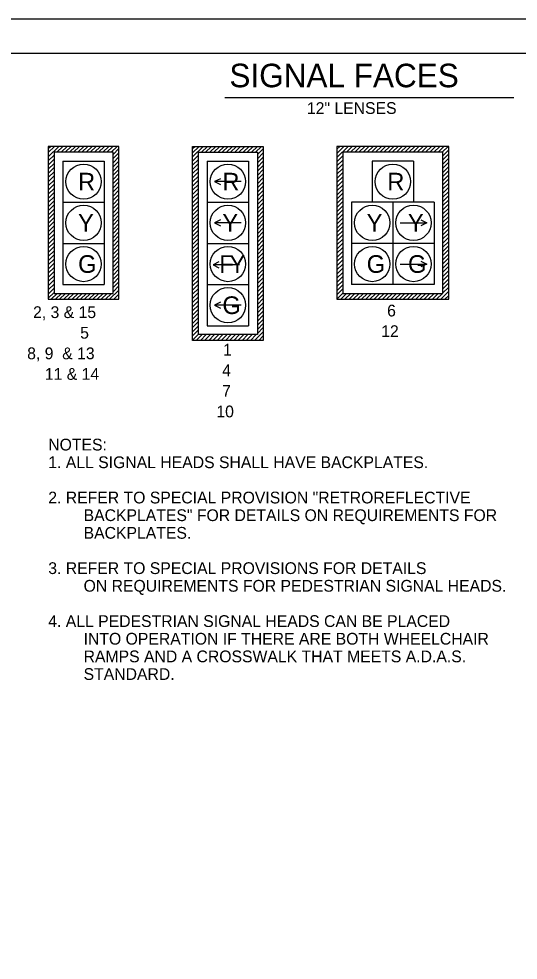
# Model space of a CAD drawing. Extents: x 1712074 to 1713074, y 558397 to 559037.
# Drawn here: x 1712248.4 to 1712417.9, y 558716.9 to 559037 of the extents above; entities that cross this region are included whole.
import ezdxf

# ---------------------------------------------------------------- set-up
doc = ezdxf.new("R2010")
doc.units = 0
for name, color, linetype in [('R_Border', 7, 'Continuous'), ('R_No Plot', 7, 'Continuous'), ('T_Drafting', 7, 'Continuous'), ('T_Notes', 7, 'Continuous')]:
    doc.layers.add(name, color=color, linetype=linetype)

msp = doc.modelspace()

# ---------------------------------------------------------------- linework, layer by layer
at = {"layer": 'R_Border'}
msp.add_line((1712111.35, 559025.27), (1713059.89, 559025.27), dxfattribs=at)
at = {"layer": 'R_No Plot'}
msp.add_line((1712074.14, 559036.95), (1713074.14, 559036.95), dxfattribs=at)
msp.add_lwpolyline([(1712074.12, 559036.95), (1713074.14, 559036.95), (1713074.14, 558396.94), (1712074.12, 558396.94)], close=True, dxfattribs=at)
at = {"layer": 'T_Drafting'}
for p, q in [((1712282.36, 558993.6), (1712258.36, 558993.6)), ((1712258.36, 558993.6), (1712258.36, 558941.6)), ((1712258.36, 558990.05), (1712261.91, 558993.6)), ((1712258.36, 558991.46), (1712260.49, 558993.6)), ((1712258.36, 558992.88), (1712259.08, 558993.6)), ((1712261.32, 558991.6), (1712263.32, 558993.6)), ((1712262.73, 558991.6), (1712264.73, 558993.6)), ((1712264.15, 558991.6), (1712266.15, 558993.6)), ((1712265.56, 558991.6), (1712267.56, 558993.6)), ((1712266.98, 558991.6), (1712268.98, 558993.6)), ((1712268.39, 558991.6), (1712270.39, 558993.6)), ((1712269.81, 558991.6), (1712271.81, 558993.6)), ((1712271.22, 558991.6), (1712273.22, 558993.6)), ((1712272.63, 558991.6), (1712274.63, 558993.6)), ((1712274.05, 558991.6), (1712276.05, 558993.6)), ((1712275.46, 558991.6), (1712277.46, 558993.6)), ((1712276.88, 558991.6), (1712278.88, 558993.6)), ((1712278.29, 558991.6), (1712280.29, 558993.6)), ((1712279.71, 558991.6), (1712281.71, 558993.6)), ((1712282.36, 558941.6), (1712282.36, 558993.6)), ((1712307.36, 558927.6), (1712307.36, 558993.6)), ((1712307.36, 558993.6), (1712331.36, 558993.6)), ((1712307.36, 558989.99), (1712310.97, 558993.6)), ((1712307.36, 558991.4), (1712309.55, 558993.6)), ((1712307.36, 558992.82), (1712308.14, 558993.6)), ((1712310.38, 558991.6), (1712312.38, 558993.6)), ((1712311.79, 558991.6), (1712313.79, 558993.6)), ((1712313.21, 558991.6), (1712315.21, 558993.6)), ((1712314.62, 558991.6), (1712316.62, 558993.6)), ((1712316.04, 558991.6), (1712318.04, 558993.6)), ((1712317.45, 558991.6), (1712319.45, 558993.6)), ((1712318.87, 558991.6), (1712320.87, 558993.6)), ((1712320.28, 558991.6), (1712322.28, 558993.6)), ((1712321.69, 558991.6), (1712323.69, 558993.6)), ((1712323.11, 558991.6), (1712325.11, 558993.6)), ((1712324.52, 558991.6), (1712326.52, 558993.6)), ((1712325.94, 558991.6), (1712327.94, 558993.6)), ((1712327.35, 558991.6), (1712329.35, 558993.6)), ((1712328.77, 558991.6), (1712330.77, 558993.6)), ((1712331.36, 558993.6), (1712331.36, 558927.6)), ((1712394.36, 558993.6), (1712356.36, 558993.6)), ((1712356.36, 558993.6), (1712356.36, 558941.6)), ((1712356.36, 558989.78), (1712360.18, 558993.6)), ((1712356.36, 558991.19), (1712358.77, 558993.6)), ((1712356.36, 558992.6), (1712357.35, 558993.6)), ((1712359.6, 558991.6), (1712361.6, 558993.6)), ((1712361.01, 558991.6), (1712363.01, 558993.6)), ((1712362.42, 558991.6), (1712364.42, 558993.6)), ((1712363.84, 558991.6), (1712365.84, 558993.6)), ((1712365.25, 558991.6), (1712367.25, 558993.6)), ((1712366.67, 558991.6), (1712368.67, 558993.6)), ((1712368.08, 558991.6), (1712370.08, 558993.6)), ((1712369.49, 558991.6), (1712371.49, 558993.6)), ((1712370.91, 558991.6), (1712372.91, 558993.6)), ((1712372.32, 558991.6), (1712374.32, 558993.6)), ((1712373.74, 558991.6), (1712375.74, 558993.6)), ((1712375.15, 558991.6), (1712377.15, 558993.6)), ((1712376.57, 558991.6), (1712378.57, 558993.6)), ((1712377.98, 558991.6), (1712379.98, 558993.6)), ((1712379.39, 558991.6), (1712381.39, 558993.6)), ((1712380.81, 558991.6), (1712382.81, 558993.6)), ((1712382.22, 558991.6), (1712384.22, 558993.6)), ((1712383.64, 558991.6), (1712385.64, 558993.6)), ((1712385.05, 558991.6), (1712387.05, 558993.6)), ((1712386.47, 558991.6), (1712388.47, 558993.6)), ((1712387.88, 558991.6), (1712389.88, 558993.6)), ((1712389.29, 558991.6), (1712391.29, 558993.6)), ((1712390.71, 558991.6), (1712392.71, 558993.6)), ((1712392.12, 558991.6), (1712394.12, 558993.6)), ((1712394.36, 558941.6), (1712394.36, 558993.6)), ((1712258.36, 558988.64), (1712260.36, 558990.64)), ((1712280.36, 558990.84), (1712282.36, 558992.84)), ((1712280.36, 558989.42), (1712282.36, 558991.42)), ((1712307.36, 558988.58), (1712309.36, 558990.58)), ((1712329.36, 558990.78), (1712331.36, 558992.78)), ((1712329.36, 558989.36), (1712331.36, 558991.36)), ((1712392.36, 558990.42), (1712394.36, 558992.42)), ((1712392.36, 558989.01), (1712394.36, 558991.01)), ((1712258.36, 558987.22), (1712260.36, 558989.22)), ((1712258.36, 558985.81), (1712260.36, 558987.81)), ((1712263.36, 558988.6), (1712277.36, 558988.6)), ((1712263.36, 558988.6), (1712263.36, 558974.6)), ((1712277.36, 558988.6), (1712277.36, 558974.6)), ((1712280.36, 558988.01), (1712282.36, 558990.01)), ((1712280.36, 558986.59), (1712282.36, 558988.59)), ((1712280.36, 558985.18), (1712282.36, 558987.18)), ((1712307.36, 558987.16), (1712309.36, 558989.16)), ((1712307.36, 558985.75), (1712309.36, 558987.75)), ((1712312.36, 558988.6), (1712326.36, 558988.6)), ((1712312.36, 558988.6), (1712312.36, 558974.6)), ((1712326.36, 558988.6), (1712326.36, 558974.6)), ((1712329.36, 558987.95), (1712331.36, 558989.95)), ((1712329.36, 558986.53), (1712331.36, 558988.53)), ((1712356.36, 558988.36), (1712358.36, 558990.36)), ((1712356.36, 558986.95), (1712358.36, 558988.95)), ((1712356.36, 558985.53), (1712358.36, 558987.53)), ((1712382.36, 558988.6), (1712368.36, 558988.6)), ((1712368.36, 558988.6), (1712368.36, 558974.6)), ((1712382.36, 558988.6), (1712382.36, 558974.6)), ((1712392.36, 558987.59), (1712394.36, 558989.59)), ((1712392.36, 558986.18), (1712394.36, 558988.18)), ((1712258.36, 558984.39), (1712260.36, 558986.39)), ((1712258.36, 558982.98), (1712260.36, 558984.98)), ((1712280.36, 558983.77), (1712282.36, 558985.77)), ((1712280.36, 558982.35), (1712282.36, 558984.35)), ((1712307.36, 558984.33), (1712309.36, 558986.33)), ((1712307.36, 558982.92), (1712309.36, 558984.92)), ((1712329.36, 558985.12), (1712331.36, 558987.12)), ((1712329.36, 558983.71), (1712331.36, 558985.71)), ((1712329.36, 558982.29), (1712331.36, 558984.29)), ((1712356.36, 558984.12), (1712358.36, 558986.12)), ((1712356.36, 558982.7), (1712358.36, 558984.7)), ((1712392.36, 558984.76), (1712394.36, 558986.76)), ((1712392.36, 558983.35), (1712394.36, 558985.35)), ((1712258.36, 558981.56), (1712260.36, 558983.56)), ((1712258.36, 558980.15), (1712260.36, 558982.15)), ((1712280.36, 558980.94), (1712282.36, 558982.94)), ((1712280.36, 558979.52), (1712282.36, 558981.52)), ((1712307.36, 558981.5), (1712309.36, 558983.5)), ((1712307.36, 558980.09), (1712309.36, 558982.09)), ((1712323.86, 558981.6), (1712314.86, 558981.6)), ((1712329.36, 558980.88), (1712331.36, 558982.88)), ((1712329.36, 558979.46), (1712331.36, 558981.46)), ((1712356.36, 558981.29), (1712358.36, 558983.29)), ((1712356.36, 558979.88), (1712358.36, 558981.88)), ((1712392.36, 558981.93), (1712394.36, 558983.93)), ((1712392.36, 558980.52), (1712394.36, 558982.52)), ((1712392.36, 558979.11), (1712394.36, 558981.11)), ((1712258.36, 558978.74), (1712260.36, 558980.74)), ((1712258.36, 558977.32), (1712260.36, 558979.32)), ((1712258.36, 558975.91), (1712260.36, 558977.91)), ((1712280.36, 558978.11), (1712282.36, 558980.11)), ((1712280.36, 558976.69), (1712282.36, 558978.69)), ((1712307.36, 558978.68), (1712309.36, 558980.68)), ((1712307.36, 558977.26), (1712309.36, 558979.26)), ((1712307.36, 558975.85), (1712309.36, 558977.85)), ((1712329.36, 558978.05), (1712331.36, 558980.05)), ((1712329.36, 558976.63), (1712331.36, 558978.63)), ((1712356.36, 558978.46), (1712358.36, 558980.46)), ((1712356.36, 558977.05), (1712358.36, 558979.05)), ((1712356.36, 558975.63), (1712358.36, 558977.63)), ((1712392.36, 558977.69), (1712394.36, 558979.69)), ((1712392.36, 558976.28), (1712394.36, 558978.28)), ((1712258.36, 558974.49), (1712260.36, 558976.49)), ((1712258.36, 558973.08), (1712260.36, 558975.08)), ((1712263.36, 558974.6), (1712277.36, 558974.6)), ((1712263.36, 558974.6), (1712263.36, 558960.6)), ((1712277.36, 558974.6), (1712277.36, 558960.6)), ((1712280.36, 558975.28), (1712282.36, 558977.28)), ((1712280.36, 558973.87), (1712282.36, 558975.87)), ((1712280.36, 558972.45), (1712282.36, 558974.45)), ((1712307.36, 558974.43), (1712309.36, 558976.43)), ((1712307.36, 558973.02), (1712309.36, 558975.02)), ((1712312.36, 558974.6), (1712326.36, 558974.6)), ((1712312.36, 558974.6), (1712312.36, 558960.6)), ((1712326.36, 558974.6), (1712326.36, 558960.6)), ((1712329.36, 558975.22), (1712331.36, 558977.22)), ((1712329.36, 558973.81), (1712331.36, 558975.81)), ((1712329.36, 558972.39), (1712331.36, 558974.39)), ((1712356.36, 558974.22), (1712358.36, 558976.22)), ((1712356.36, 558972.8), (1712358.36, 558974.8)), ((1712375.36, 558974.6), (1712361.36, 558974.6)), ((1712361.36, 558974.6), (1712361.36, 558960.6)), ((1712375.36, 558974.6), (1712375.36, 558960.6)), ((1712389.36, 558974.6), (1712375.36, 558974.6)), ((1712375.36, 558974.6), (1712375.36, 558960.6)), ((1712389.36, 558974.6), (1712389.36, 558960.6)), ((1712392.36, 558974.86), (1712394.36, 558976.86)), ((1712392.36, 558973.45), (1712394.36, 558975.45)), ((1712258.36, 558971.67), (1712260.36, 558973.67)), ((1712258.36, 558970.25), (1712260.36, 558972.25)), ((1712280.36, 558971.04), (1712282.36, 558973.04)), ((1712280.36, 558969.62), (1712282.36, 558971.62)), ((1712307.36, 558971.6), (1712309.36, 558973.6)), ((1712307.36, 558970.19), (1712309.36, 558972.19)), ((1712329.36, 558970.98), (1712331.36, 558972.98)), ((1712329.36, 558969.56), (1712331.36, 558971.56)), ((1712356.36, 558971.39), (1712358.36, 558973.39)), ((1712356.36, 558969.98), (1712358.36, 558971.98)), ((1712392.36, 558972.04), (1712394.36, 558974.04)), ((1712392.36, 558970.62), (1712394.36, 558972.62)), ((1712392.36, 558969.21), (1712394.36, 558971.21)), ((1712258.36, 558968.84), (1712260.36, 558970.84)), ((1712258.36, 558967.42), (1712260.36, 558969.42)), ((1712258.36, 558966.01), (1712260.36, 558968.01)), ((1712280.36, 558968.21), (1712282.36, 558970.21)), ((1712280.36, 558966.8), (1712282.36, 558968.8)), ((1712307.36, 558968.78), (1712309.36, 558970.78)), ((1712307.36, 558967.36), (1712309.36, 558969.36)), ((1712329.36, 558968.15), (1712331.36, 558970.15)), ((1712329.36, 558966.73), (1712331.36, 558968.73)), ((1712356.36, 558968.56), (1712358.36, 558970.56)), ((1712356.36, 558967.15), (1712358.36, 558969.15)), ((1712392.36, 558967.79), (1712394.36, 558969.79)), ((1712392.36, 558966.38), (1712394.36, 558968.38)), ((1712258.36, 558964.59), (1712260.36, 558966.59)), ((1712258.36, 558963.18), (1712260.36, 558965.18)), ((1712280.36, 558965.38), (1712282.36, 558967.38)), ((1712280.36, 558963.97), (1712282.36, 558965.97)), ((1712307.36, 558965.95), (1712309.36, 558967.95)), ((1712307.36, 558964.53), (1712309.36, 558966.53)), ((1712307.36, 558963.12), (1712309.36, 558965.12)), ((1712323.86, 558967.6), (1712314.86, 558967.6)), ((1712329.36, 558965.32), (1712331.36, 558967.32)), ((1712329.36, 558963.91), (1712331.36, 558965.91)), ((1712356.36, 558965.73), (1712358.36, 558967.73)), ((1712356.36, 558964.32), (1712358.36, 558966.32)), ((1712356.36, 558962.91), (1712358.36, 558964.91)), ((1712377.86, 558967.6), (1712386.86, 558967.6)), ((1712392.36, 558964.96), (1712394.36, 558966.96)), ((1712392.36, 558963.55), (1712394.36, 558965.55)), ((1712258.36, 558961.77), (1712260.36, 558963.77)), ((1712258.36, 558960.35), (1712260.36, 558962.35)), ((1712280.36, 558962.55), (1712282.36, 558964.55)), ((1712280.36, 558961.14), (1712282.36, 558963.14)), ((1712280.36, 558959.72), (1712282.36, 558961.72)), ((1712307.36, 558961.71), (1712309.36, 558963.71)), ((1712307.36, 558960.29), (1712309.36, 558962.29)), ((1712329.36, 558962.49), (1712331.36, 558964.49)), ((1712329.36, 558961.08), (1712331.36, 558963.08)), ((1712329.36, 558959.66), (1712331.36, 558961.66)), ((1712356.36, 558961.49), (1712358.36, 558963.49)), ((1712356.36, 558960.08), (1712358.36, 558962.08)), ((1712392.36, 558962.14), (1712394.36, 558964.14)), ((1712392.36, 558960.72), (1712394.36, 558962.72)), ((1712258.36, 558958.94), (1712260.36, 558960.94)), ((1712258.36, 558957.52), (1712260.36, 558959.52)), ((1712263.36, 558960.6), (1712277.36, 558960.6)), ((1712263.36, 558960.6), (1712263.36, 558946.6)), ((1712277.36, 558960.6), (1712277.36, 558946.6)), ((1712280.36, 558958.31), (1712282.36, 558960.31)), ((1712280.36, 558956.9), (1712282.36, 558958.9)), ((1712307.36, 558958.88), (1712309.36, 558960.88)), ((1712307.36, 558957.46), (1712309.36, 558959.46)), ((1712312.36, 558960.6), (1712326.36, 558960.6)), ((1712312.36, 558960.6), (1712312.36, 558946.6)), ((1712326.36, 558960.6), (1712326.36, 558946.6)), ((1712329.36, 558958.25), (1712331.36, 558960.25)), ((1712329.36, 558956.84), (1712331.36, 558958.84)), ((1712356.36, 558958.66), (1712358.36, 558960.66)), ((1712356.36, 558957.25), (1712358.36, 558959.25)), ((1712375.36, 558960.6), (1712361.36, 558960.6)), ((1712361.36, 558960.6), (1712361.36, 558946.6)), ((1712389.36, 558960.6), (1712375.36, 558960.6)), ((1712375.36, 558960.6), (1712375.36, 558946.6)), ((1712375.36, 558960.6), (1712375.36, 558946.6)), ((1712389.36, 558960.6), (1712389.36, 558946.6)), ((1712392.36, 558959.31), (1712394.36, 558961.31)), ((1712392.36, 558957.89), (1712394.36, 558959.89)), ((1712392.36, 558956.48), (1712394.36, 558958.48)), ((1712258.36, 558956.11), (1712260.36, 558958.11)), ((1712258.36, 558954.69), (1712260.36, 558956.69)), ((1712258.36, 558953.28), (1712260.36, 558955.28)), ((1712280.36, 558955.48), (1712282.36, 558957.48)), ((1712280.36, 558954.07), (1712282.36, 558956.07)), ((1712307.36, 558956.05), (1712309.36, 558958.05)), ((1712307.36, 558954.63), (1712309.36, 558956.63)), ((1712307.36, 558953.22), (1712309.36, 558955.22)), ((1712329.36, 558955.42), (1712331.36, 558957.42)), ((1712329.36, 558954.01), (1712331.36, 558956.01)), ((1712356.36, 558955.83), (1712358.36, 558957.83)), ((1712356.36, 558954.42), (1712358.36, 558956.42)), ((1712392.36, 558955.06), (1712394.36, 558957.06)), ((1712392.36, 558953.65), (1712394.36, 558955.65)), ((1712258.36, 558951.87), (1712260.36, 558953.87)), ((1712258.36, 558950.45), (1712260.36, 558952.45)), ((1712280.36, 558952.65), (1712282.36, 558954.65)), ((1712280.36, 558951.24), (1712282.36, 558953.24)), ((1712307.36, 558951.81), (1712309.36, 558953.81)), ((1712307.36, 558950.39), (1712309.36, 558952.39)), ((1712323.33, 558953.32), (1712314.33, 558953.32)), ((1712329.36, 558952.59), (1712331.36, 558954.59)), ((1712329.36, 558951.18), (1712331.36, 558953.18)), ((1712356.36, 558953.01), (1712358.36, 558955.01)), ((1712356.36, 558951.59), (1712358.36, 558953.59)), ((1712356.36, 558950.18), (1712358.36, 558952.18)), ((1712377.86, 558953.6), (1712386.86, 558953.6)), ((1712392.36, 558952.24), (1712394.36, 558954.24)), ((1712392.36, 558950.82), (1712394.36, 558952.82)), ((1712258.36, 558949.04), (1712260.36, 558951.04)), ((1712258.36, 558947.62), (1712260.36, 558949.62)), ((1712280.36, 558949.82), (1712282.36, 558951.82)), ((1712280.36, 558948.41), (1712282.36, 558950.41)), ((1712280.36, 558947), (1712282.36, 558949)), ((1712307.36, 558948.98), (1712309.36, 558950.98)), ((1712307.36, 558947.56), (1712309.36, 558949.56)), ((1712329.36, 558949.76), (1712331.36, 558951.76)), ((1712329.36, 558948.35), (1712331.36, 558950.35)), ((1712329.36, 558946.94), (1712331.36, 558948.94)), ((1712356.36, 558948.76), (1712358.36, 558950.76)), ((1712356.36, 558947.35), (1712358.36, 558949.35)), ((1712392.36, 558949.41), (1712394.36, 558951.41)), ((1712392.36, 558947.99), (1712394.36, 558949.99)), ((1712258.36, 558946.21), (1712260.36, 558948.21)), ((1712258.36, 558944.8), (1712260.36, 558946.8)), ((1712263.36, 558946.6), (1712277.36, 558946.6)), ((1712280.36, 558945.58), (1712282.36, 558947.58)), ((1712280.36, 558944.17), (1712282.36, 558946.17)), ((1712307.36, 558946.15), (1712309.36, 558948.15)), ((1712307.36, 558944.73), (1712309.36, 558946.73)), ((1712312.36, 558946.6), (1712326.36, 558946.6)), ((1712312.36, 558946.6), (1712312.36, 558932.6)), ((1712326.36, 558946.6), (1712326.36, 558932.6)), ((1712329.36, 558945.52), (1712331.36, 558947.52)), ((1712329.36, 558944.11), (1712331.36, 558946.11)), ((1712356.36, 558945.93), (1712358.36, 558947.93)), ((1712356.36, 558944.52), (1712358.36, 558946.52)), ((1712375.36, 558946.6), (1712361.36, 558946.6)), ((1712389.36, 558946.6), (1712375.36, 558946.6)), ((1712392.36, 558946.58), (1712394.36, 558948.58)), ((1712392.36, 558945.17), (1712394.36, 558947.17)), ((1712392.36, 558943.75), (1712394.36, 558945.75)), ((1712258.36, 558943.38), (1712260.36, 558945.38)), ((1712258.36, 558941.97), (1712260.36, 558943.97)), ((1712259.4, 558941.6), (1712261.4, 558943.6)), ((1712260.82, 558941.6), (1712262.82, 558943.6)), ((1712262.23, 558941.6), (1712264.23, 558943.6)), ((1712263.65, 558941.6), (1712265.65, 558943.6)), ((1712265.06, 558941.6), (1712267.06, 558943.6)), ((1712266.47, 558941.6), (1712268.47, 558943.6)), ((1712267.89, 558941.6), (1712269.89, 558943.6)), ((1712269.3, 558941.6), (1712271.3, 558943.6)), ((1712270.72, 558941.6), (1712272.72, 558943.6)), ((1712272.13, 558941.6), (1712274.13, 558943.6)), ((1712273.55, 558941.6), (1712275.55, 558943.6)), ((1712274.96, 558941.6), (1712276.96, 558943.6)), ((1712276.37, 558941.6), (1712278.37, 558943.6)), ((1712277.79, 558941.6), (1712279.79, 558943.6)), ((1712279.2, 558941.6), (1712282.36, 558944.75)), ((1712280.62, 558941.6), (1712282.36, 558943.34)), ((1712307.36, 558943.32), (1712309.36, 558945.32)), ((1712307.36, 558941.91), (1712309.36, 558943.91)), ((1712307.36, 558940.49), (1712309.36, 558942.49)), ((1712329.36, 558942.69), (1712331.36, 558944.69)), ((1712329.36, 558941.28), (1712331.36, 558943.28)), ((1712356.36, 558943.11), (1712358.36, 558945.11)), ((1712356.36, 558941.69), (1712358.36, 558943.69)), ((1712357.68, 558941.6), (1712359.68, 558943.6)), ((1712359.09, 558941.6), (1712361.09, 558943.6)), ((1712360.51, 558941.6), (1712362.51, 558943.6)), ((1712361.92, 558941.6), (1712363.92, 558943.6)), ((1712363.34, 558941.6), (1712365.34, 558943.6)), ((1712364.75, 558941.6), (1712366.75, 558943.6)), ((1712366.16, 558941.6), (1712368.16, 558943.6)), ((1712367.58, 558941.6), (1712369.58, 558943.6)), ((1712368.99, 558941.6), (1712370.99, 558943.6)), ((1712370.41, 558941.6), (1712372.41, 558943.6)), ((1712371.82, 558941.6), (1712373.82, 558943.6)), ((1712373.23, 558941.6), (1712375.23, 558943.6)), ((1712374.65, 558941.6), (1712376.65, 558943.6)), ((1712376.06, 558941.6), (1712378.06, 558943.6)), ((1712377.48, 558941.6), (1712379.48, 558943.6)), ((1712378.89, 558941.6), (1712380.89, 558943.6)), ((1712380.31, 558941.6), (1712382.31, 558943.6)), ((1712381.72, 558941.6), (1712383.72, 558943.6)), ((1712383.13, 558941.6), (1712385.13, 558943.6)), ((1712384.55, 558941.6), (1712386.55, 558943.6)), ((1712385.96, 558941.6), (1712387.96, 558943.6)), ((1712387.38, 558941.6), (1712389.38, 558943.6)), ((1712388.79, 558941.6), (1712390.79, 558943.6)), ((1712390.21, 558941.6), (1712392.21, 558943.6)), ((1712391.62, 558941.6), (1712394.36, 558944.34)), ((1712393.03, 558941.6), (1712394.36, 558942.92)), ((1712258.36, 558941.6), (1712282.36, 558941.6)), ((1712282.03, 558941.6), (1712282.36, 558941.93)), ((1712307.36, 558939.08), (1712309.36, 558941.08)), ((1712307.36, 558937.66), (1712309.36, 558939.66)), ((1712323.86, 558939.6), (1712314.86, 558939.6)), ((1712329.36, 558939.86), (1712331.36, 558941.86)), ((1712329.36, 558938.45), (1712331.36, 558940.45)), ((1712356.36, 558941.6), (1712394.36, 558941.6)), ((1712307.36, 558936.25), (1712309.36, 558938.25)), ((1712307.36, 558934.84), (1712309.36, 558936.84)), ((1712329.36, 558937.04), (1712331.36, 558939.04)), ((1712329.36, 558935.62), (1712331.36, 558937.62)), ((1712329.36, 558934.21), (1712331.36, 558936.21)), ((1712307.36, 558933.42), (1712309.36, 558935.42)), ((1712307.36, 558932.01), (1712309.36, 558934.01)), ((1712329.36, 558932.79), (1712331.36, 558934.79)), ((1712329.36, 558931.38), (1712331.36, 558933.38)), ((1712307.36, 558930.59), (1712309.36, 558932.59)), ((1712307.36, 558929.18), (1712309.36, 558931.18)), ((1712307.36, 558927.76), (1712309.36, 558929.76)), ((1712308.61, 558927.6), (1712310.61, 558929.6)), ((1712310.02, 558927.6), (1712312.02, 558929.6)), ((1712311.43, 558927.6), (1712313.43, 558929.6)), ((1712312.36, 558932.6), (1712326.36, 558932.6)), ((1712312.85, 558927.6), (1712314.85, 558929.6)), ((1712314.26, 558927.6), (1712316.26, 558929.6)), ((1712315.68, 558927.6), (1712317.68, 558929.6)), ((1712317.09, 558927.6), (1712319.09, 558929.6)), ((1712318.51, 558927.6), (1712320.51, 558929.6)), ((1712319.92, 558927.6), (1712321.92, 558929.6)), ((1712321.33, 558927.6), (1712323.33, 558929.6)), ((1712322.75, 558927.6), (1712324.75, 558929.6)), ((1712324.16, 558927.6), (1712326.16, 558929.6)), ((1712325.58, 558927.6), (1712327.58, 558929.6)), ((1712326.99, 558927.6), (1712328.99, 558929.6)), ((1712328.41, 558927.6), (1712331.36, 558930.55)), ((1712329.36, 558929.97), (1712331.36, 558931.97)), ((1712331.36, 558927.6), (1712307.36, 558927.6)), ((1712329.82, 558927.6), (1712331.36, 558929.14)), ((1712331.23, 558927.6), (1712331.36, 558927.72))]:
    msp.add_line(p, q, dxfattribs=at)
for points in [[(1712280.36, 558943.6), (1712280.36, 558991.6), (1712260.36, 558991.6), (1712260.36, 558943.6)], [(1712309.36, 558929.6), (1712309.36, 558991.6), (1712329.36, 558991.6), (1712329.36, 558929.6)], [(1712392.36, 558991.6), (1712358.36, 558991.6), (1712358.36, 558943.6), (1712392.36, 558943.6)]]:
    msp.add_lwpolyline(points, close=True, dxfattribs=at)
for points in [[(1712316.86, 558982.6), (1712314.86, 558981.6), (1712316.86, 558980.6)], [(1712316.86, 558968.6), (1712314.86, 558967.6), (1712316.86, 558966.6)], [(1712384.86, 558968.6), (1712386.86, 558967.6), (1712384.86, 558966.6)], [(1712316.33, 558954.32), (1712314.33, 558953.32), (1712316.33, 558952.32)], [(1712384.86, 558954.6), (1712386.86, 558953.6), (1712384.86, 558952.6)], [(1712316.86, 558940.6), (1712314.86, 558939.6), (1712316.86, 558938.6)]]:
    msp.add_lwpolyline(points, dxfattribs=at)
for centre in [(1712270.36, 558981.6), (1712319.36, 558981.6), (1712375.36, 558981.6), (1712270.36, 558967.6), (1712319.36, 558967.6), (1712368.36, 558967.6), (1712382.36, 558967.6), (1712270.36, 558953.6), (1712319.36, 558953.6), (1712368.36, 558953.6), (1712382.36, 558953.6), (1712319.36, 558939.6)]:
    msp.add_circle(centre, 6, dxfattribs=at)
at = {"layer": 'T_Notes'}
msp.add_line((1712318.27, 559010.22), (1712416.45, 559010.22), dxfattribs=at)

# ---------------------------------------------------------------- texts
at = {"layer": 'T_Drafting'}
msp.add_text('12" LENSES', height=4, rotation=0.072, dxfattribs=at).set_placement((1712346.19, 559004.59))
for s, p in [('R', (1712268.49, 558978.6)), ('R', (1712317.49, 558978.6)), ('R', (1712373.49, 558978.6)), ('Y', (1712268.47, 558964.6)), ('Y', (1712317.47, 558964.6)), ('Y', (1712366.47, 558964.6)), ('Y', (1712380.47, 558964.6)), ('G', (1712268.49, 558950.6)), ('F', (1712316.45, 558950.6)), ('Y', (1712319.88, 558950.6)), ('G', (1712366.49, 558950.6)), ('G', (1712380.49, 558950.6)), ('G', (1712317.49, 558936.6))]:
    msp.add_text(s, height=6, dxfattribs=at).set_placement(p)
at = {"layer": 'T_Notes'}
for s, height, p in [('SIGNAL FACES', 8, (1712319.87, 559013.69)), ('2, 3 & 15', 4, (1712253.2, 558935.23)), ('6', 4, (1712373.42, 558935.77)), ('12', 4, (1712371.42, 558928.77)), ('5 ', 4, (1712269.2, 558928.23)), ('1', 4, (1712317.7, 558922.47)), ('8, 9  & 13', 4, (1712251.2, 558921.23)), ('11 & 14', 4, (1712257.2, 558914.23)), ('4', 4, (1712317.41, 558915.47)), ('7', 4, (1712317.4, 558908.47)), ('10', 4, (1712315.44, 558901.47)), ('NOTES:', 4, (1712258.36, 558890.21)), ('1. ALL SIGNAL HEADS SHALL HAVE BACKPLATES.', 4, (1712258.36, 558884.21)), ('2. REFER TO SPECIAL PROVISION "RETROREFLECTIVE', 4, (1712258.36, 558872.21)), ('BACKPLATES" FOR DETAILS ON REQUIREMENTS FOR ', 4, (1712270.36, 558866.21)), ('BACKPLATES.', 4, (1712270.36, 558860.21)), ('3. REFER TO SPECIAL PROVISIONS FOR DETAILS', 4, (1712258.36, 558848.21)), ('ON REQUIREMENTS FOR PEDESTRIAN SIGNAL HEADS.', 4, (1712270.36, 558842.21)), ('4. ALL PEDESTRIAN SIGNAL HEADS CAN BE PLACED', 4, (1712258.36, 558830.21)), ('INTO OPERATION IF THERE ARE BOTH WHEELCHAIR', 4, (1712270.36, 558824.21)), ('RAMPS AND A CROSSWALK THAT MEETS A.D.A.S.', 4, (1712270.36, 558818.21)), ('STANDARD.', 4, (1712270.36, 558812.21))]:
    msp.add_text(s, height=height, dxfattribs=at).set_placement(p)

doc.saveas('drawing.dxf')
